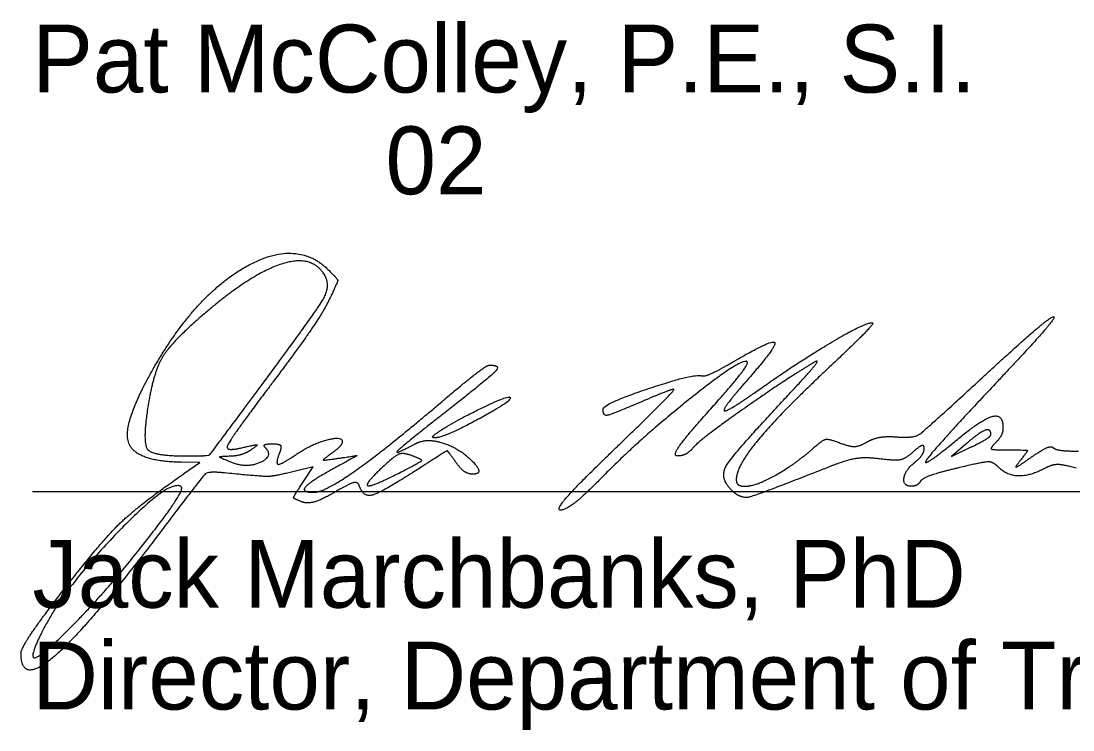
# Model space of a CAD drawing. Extents: x -5.6 to 34, y 0 to 22.
# Drawn here: x 26.293 to 28.462, y 5.434 to 6.897 of the extents above; entities that cross this region are included whole.
import ezdxf

# ---------------------------------------------------------------- set-up
doc = ezdxf.new("R2010")
doc.units = 0
doc.layers.add('SH_Data', color=7, linetype='Continuous')
doc.layers.add('SH_Text', color=7, linetype='Continuous')

msp = doc.modelspace()

# ---------------------------------------------------------------- linework, layer by layer
at = {"layer": 'SH_Data'}
msp.add_line((26.316, 5.9267), (29.816, 5.9267), dxfattribs=at)
at = {"layer": 'SH_Text'}
for p, q in [((26.7783, 6.1317), (26.7783, 6.1317)), ((27.1437, 6.0419), (27.1437, 6.0419)), ((28.2926, 6.0439), (28.2926, 6.0439)), ((27.5155, 6.0128), (27.5155, 6.0128)), ((27.0989, 6.0002), (27.0989, 6.0002))]:
    msp.add_line(p, q, dxfattribs=at)
for points in [[(28.2409, 6.0242), (28.2114, 5.9986), (28.252, 6.0183)], [(26.6307, 5.9648), (26.6614, 5.986), (26.6235, 5.9867)], [(26.8736, 5.9449), (26.8948, 5.9773), (26.8531, 5.9672)]]:
    msp.add_lwpolyline(points, dxfattribs=at)
for points in [[(26.567, 6.1825), (26.6533, 6.3329), (26.8614, 6.4489), (26.9271, 6.3832)], [(26.9181, 6.374), (26.8921, 6.4161), (26.766, 6.3749), (26.6707, 6.2933)], [(26.9271, 6.3832), (26.9458, 6.3645), (26.9459, 6.3594), (26.9275, 6.321)], [(26.7783, 6.1317), (26.8997, 6.2952), (26.9321, 6.3514), (26.9181, 6.374)], [(26.9275, 6.321), (26.9166, 6.298), (26.8649, 6.2224), (26.8126, 6.1531)], [(26.6707, 6.2933), (26.604, 6.2362), (26.5652, 6.1721), (26.5541, 6.1009)], [(27.8207, 6.141), (27.9013, 6.1976), (28.0326, 6.2748), (28.0483, 6.2748)], [(28.0483, 6.2748), (28.0532, 6.2748), (28.0119, 6.2322), (27.9565, 6.1801)], [(28.275, 6.1614), (28.35, 6.2305), (28.4161, 6.2871), (28.4218, 6.2872)], [(28.4218, 6.2872), (28.4275, 6.2872), (28.3755, 6.2271), (28.3062, 6.1535)], [(27.7618, 6.1945), (27.8405, 6.2406), (27.8528, 6.2274), (27.7935, 6.1601)], [(26.6235, 5.9867), (26.5256, 5.9883), (26.5022, 6.0695), (26.567, 6.1825)], [(27.1571, 6.109), (27.2076, 6.1519), (27.2531, 6.187), (27.2582, 6.1871)], [(27.2582, 6.1871), (27.2831, 6.1876), (27.2597, 6.1621), (27.1739, 6.0948)], [(27.7899, 6.1942), (27.7802, 6.2038), (27.5705, 6.0369), (27.4926, 5.9576)], [(27.9301, 6.1938), (27.8811, 6.166), (27.6927, 6.0338), (27.6795, 6.0178)], [(27.6961, 6.1652), (27.7017, 6.1634), (27.7312, 6.1766), (27.7618, 6.1945)], [(27.712, 6.0938), (27.7583, 6.1456), (27.7933, 6.1907), (27.7899, 6.1942)], [(27.8649, 6.1148), (27.9111, 6.1641), (27.9404, 6.1996), (27.9301, 6.1938)], [(27.4928, 6.0967), (27.493, 6.1072), (27.6804, 6.1704), (27.6961, 6.1652)], [(27.9565, 6.1801), (27.8569, 6.0864), (27.7676, 5.9782), (27.7676, 5.9513)], [(28.1, 6.039), (28.1335, 6.0362), (28.157, 6.0526), (28.275, 6.1614)], [(26.8126, 6.1531), (26.7604, 6.0837), (26.7176, 6.0231), (26.7176, 6.0183)], [(27.7935, 6.1601), (27.7655, 6.1283), (27.7426, 6.0986), (27.7426, 6.0941)], [(27.7426, 6.0941), (27.7426, 6.0897), (27.7778, 6.1108), (27.8207, 6.141)], [(28.3062, 6.1535), (28.1766, 6.0159), (28.1445, 5.9687), (28.2267, 6.0364)], [(26.6322, 5.9998), (26.6789, 5.9998), (26.6834, 6.0039), (26.7783, 6.1317)], [(27.1437, 6.0419), (27.164, 6.0597), (27.2961, 6.1255), (27.3012, 6.1204)], [(27.3012, 6.1204), (27.3074, 6.1142), (27.1648, 6.0373), (27.1471, 6.0373)], [(27.5155, 6.0128), (27.5865, 6.0813), (27.6418, 6.1373), (27.6384, 6.1373)], [(27.6384, 6.1373), (27.635, 6.1373), (27.6059, 6.1261), (27.5739, 6.1123)], [(26.5541, 6.1009), (26.5427, 6.0275), (26.5641, 5.9998), (26.6322, 5.9998)], [(26.8958, 5.9248), (26.9189, 5.9248), (27.0449, 6.0136), (27.1571, 6.109)], [(27.5739, 6.1123), (27.5113, 6.0855), (27.4925, 6.0819), (27.4928, 6.0967)], [(27.7578, 5.9292), (27.7326, 5.9544), (27.7616, 6.0045), (27.8649, 6.1148)], [(27.1739, 6.0948), (27.0806, 6.0218), (27.0592, 6.0002), (27.1031, 6.0237)], [(27.6462, 5.9998), (27.6359, 5.9998), (27.6648, 6.0411), (27.712, 6.0938)], [(28.2267, 6.0364), (28.2751, 6.0763), (28.3176, 6.0867), (28.3176, 6.0586)], [(28.2926, 6.0439), (28.2926, 6.0574), (28.2685, 6.0482), (28.2409, 6.0242)], [(28.3176, 6.0586), (28.3176, 6.0496), (28.3109, 6.0356), (28.3026, 6.0273)], [(26.8617, 6.0042), (26.8906, 6.024), (26.9551, 6.0415), (26.9551, 6.0295)], [(27.1031, 6.0237), (27.1157, 6.0305), (27.1396, 6.0326), (27.1562, 6.0284)], [(27.1471, 6.0373), (27.1424, 6.0373), (27.1408, 6.0394), (27.1437, 6.0419)], [(27.9251, 6.0148), (27.9454, 6.0328), (27.9583, 6.0355), (27.982, 6.0265)], [(28.037, 6.0285), (28.0504, 6.0361), (28.0788, 6.0408), (28.1, 6.039)], [(28.252, 6.0183), (28.2743, 6.0291), (28.2926, 6.0406), (28.2926, 6.0439)], [(26.7176, 6.0183), (26.7176, 6.0135), (26.7331, 6.0132), (26.752, 6.0176)], [(26.7676, 6.0129), (26.7573, 6.0059), (26.7376, 5.9997), (26.7239, 5.9992)], [(26.728, 5.9865), (26.7579, 5.9746), (26.8141, 5.9991), (26.7967, 6.0166)], [(26.752, 6.0176), (26.7775, 6.0235), (26.7815, 6.0223), (26.7676, 6.0129)], [(26.7967, 6.0166), (26.7922, 6.0211), (26.7984, 6.0248), (26.8106, 6.0248)], [(26.8106, 6.0248), (26.8252, 6.0248), (26.8303, 6.0184), (26.8256, 6.0061)], [(26.9551, 6.0295), (26.9551, 6.025), (26.9454, 6.0142), (26.9335, 6.0055)], [(27.1893, 5.987), (27.1724, 6.011), (27.1704, 6.0106), (27.1046, 5.9682)], [(27.1562, 6.0284), (27.1923, 6.0192), (27.2507, 5.9623), (27.224, 5.9623)], [(27.4051, 5.888), (27.3948, 5.8882), (27.4445, 5.9444), (27.5155, 6.0128)], [(27.6795, 6.0178), (27.6713, 6.0079), (27.6563, 5.9998), (27.6462, 5.9998)], [(27.7856, 5.9373), (27.8074, 5.9373), (27.8887, 5.9825), (27.9251, 6.0148)], [(27.982, 6.0265), (28.0022, 6.0188), (28.021, 6.0195), (28.037, 6.0285)], [(28.1551, 6.0158), (28.1551, 6.0229), (28.145, 6.0195), (28.1325, 6.0083)], [(28.1364, 5.9873), (28.1467, 5.9959), (28.1551, 6.0087), (28.1551, 6.0158)], [(28.3026, 6.0273), (28.2909, 6.0156), (28.2968, 6.0123), (28.3291, 6.0123)], [(28.3291, 6.0123), (28.3667, 6.0123), (28.369, 6.0103), (28.3535, 5.9909)], [(28.3753, 5.9968), (28.3967, 6.0118), (28.4174, 6.0209), (28.4213, 6.0169)], [(28.4213, 6.0169), (28.4252, 6.013), (28.4485, 6.0098), (28.473, 6.0098)], [(26.7239, 5.9992), (26.7015, 5.9983), (26.7019, 5.997), (26.728, 5.9865)], [(26.8256, 6.0061), (26.8167, 5.9828), (26.8295, 5.9821), (26.8617, 6.0042)], [(26.9335, 6.0055), (26.9146, 5.9917), (26.9166, 5.9904), (26.9491, 5.9953)], [(26.9491, 5.9953), (26.9859, 6.0009), (26.9858, 6.0006), (26.9403, 5.9755)], [(27.0989, 6.0002), (27.0816, 6.0066), (27.0651, 6.0014), (27.0457, 5.9837)], [(27.0707, 5.9639), (27.1171, 5.9876), (27.1207, 5.9922), (27.0989, 6.0002)], [(28.063, 5.9938), (28.0338, 5.9976), (27.994, 5.9911), (27.9575, 5.9767)], [(28.1325, 6.0083), (28.1169, 5.9941), (28.0956, 5.9897), (28.063, 5.9938)], [(28.1294, 5.9373), (28.111, 5.9373), (28.1156, 5.9701), (28.1364, 5.9873)], [(28.308, 5.9769), (28.2969, 5.988), (28.2769, 5.9875), (28.2237, 5.9748)], [(28.3535, 5.9909), (28.3415, 5.9759), (28.348, 5.9777), (28.3753, 5.9968)], [(26.7119, 5.9649), (26.6785, 5.9682), (26.6667, 5.9577), (26.5901, 5.8561)], [(26.8531, 5.9672), (26.8127, 5.9574), (26.7904, 5.9571), (26.7119, 5.9649)], [(26.9403, 5.9755), (26.8892, 5.9473), (26.8695, 5.9248), (26.8958, 5.9248)], [(27.1046, 5.9682), (27.0357, 5.9239), (26.9983, 5.9141), (26.9901, 5.9385)], [(27.0457, 5.9837), (27.0015, 5.9432), (27.0127, 5.9343), (27.0707, 5.9639)], [(27.224, 5.9623), (27.2144, 5.9623), (27.1988, 5.9734), (27.1893, 5.987)], [(27.9575, 5.9767), (27.8114, 5.919), (27.7764, 5.9107), (27.7578, 5.9292)], [(28.2237, 5.9748), (28.1853, 5.9656), (28.1511, 5.9534), (28.1475, 5.9477)], [(28.4043, 5.9744), (28.3736, 5.9579), (28.3257, 5.9592), (28.308, 5.9769)], [(28.4688, 5.9745), (28.4419, 5.9822), (28.4188, 5.9821), (28.4043, 5.9744)], [(26.3797, 5.7226), (26.4574, 5.823), (26.5375, 5.9003), (26.6307, 5.9648)], [(26.8724, 5.9049), (26.8542, 5.9119), (26.8543, 5.9155), (26.8736, 5.9449)], [(26.9901, 5.9385), (26.9873, 5.947), (26.9681, 5.9419), (26.939, 5.9247)], [(27.4926, 5.9576), (27.4548, 5.9191), (27.4154, 5.8878), (27.4051, 5.888)], [(27.7676, 5.9513), (27.7676, 5.9436), (27.7757, 5.9373), (27.7856, 5.9373)], [(28.1475, 5.9477), (28.144, 5.942), (28.1358, 5.9373), (28.1294, 5.9373)], [(26.6235, 5.9355), (26.6026, 5.9565), (26.3841, 5.7308), (26.3378, 5.6404)], [(26.4079, 5.6592), (26.4755, 5.7283), (26.6312, 5.9279), (26.6235, 5.9355)], [(26.939, 5.9247), (26.9134, 5.9096), (26.8834, 5.9007), (26.8724, 5.9049)], [(26.5901, 5.8561), (26.4377, 5.654), (26.2926, 5.5253), (26.2926, 5.5923)], [(26.2926, 5.5923), (26.2926, 5.602), (26.3318, 5.6606), (26.3797, 5.7226)], [(26.3378, 5.6404), (26.3065, 5.5795), (26.3382, 5.5879), (26.4079, 5.6592)]]:
    msp.add_open_spline(points, degree=2, dxfattribs=at)

# ---------------------------------------------------------------- texts
for s, p in [('Pat McColley, P.E., S.I.', (26.316, 6.7497)), ('              02', (26.316, 6.5397)), ('Jack Marchbanks, PhD', (26.316, 5.6867)), ('Director, Department of Transportation', (26.316, 5.4767))]:
    msp.add_text(s, height=0.14, dxfattribs=at).set_placement(p)

doc.saveas('drawing.dxf')
